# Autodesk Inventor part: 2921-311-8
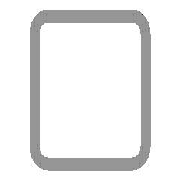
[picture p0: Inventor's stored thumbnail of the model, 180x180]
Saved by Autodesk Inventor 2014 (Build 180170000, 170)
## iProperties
IsCustomPart: 1
Company: NHTSA/VRTC
Created: 2012-02
Part Number: 2921-311-8
Material: Steel, Mild
Description: BENCH FRAME TUBE #8
Document SubType Name: Modeling
Standard: AISC
Designer: Dave Walker
Standards Organization: ANSI
Language: en-US
Size Designation: 1-1/2x1-1/2x1/8 - 24.56
Categories: <MemberInstance><Categories><Category DisplayName="Structural Shapes" InternalName="089c4875-fa83-4c05-b084-43b9cc11f5ed" Mnemonic="GRDR"><CategoryParameter Dis
Stock Number: T.S. 1 1/2 x 1 1/2 x 1/8 x 623.8mm (24.56")
Density: 1 g/cm^3
Project: CHILD SIDE IMPACT SLED
Appearance: Steel
G_L: 24.560 in
Author: Dave Walker
Title: Bench Frame Tube #8
Subject: Child Side Impact Sled
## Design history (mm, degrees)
node "Start plane"
node "End plane"
sketch "Sketch"
  geometry: L1 (-19.05, -12.7)-(-19.05, 12.7); L2 (-12.7, 19.05)-(12.7, 19.05); L3 (19.05, 12.7)-(19.05, -12.7); L4 (12.7, -19.05)-(-12.7, -19.05); L5 (-12.7, 15.875)-(12.7, 15.875); L6 (15.875, 12.7)-(15.875, -12.7); L7 (12.7, -15.875)-(-12.7, -15.875); L8 (-15.875, -12.7)-(-15.875, 12.7); L9 (0, 36.948)-(0, -36.948) reference; L10 (-23.079, 0)-(23.079, 0) reference; A1 r 6.35 centre (-12.7, -12.7) between (-19.05, -12.7) and (-12.7, -19.05); A2 r 6.35 centre (-12.7, 12.7) between (-12.7, 19.05) and (-19.05, 12.7); A3 r 6.35 centre (12.7, 12.7) between (19.05, 12.7) and (12.7, 19.05); A4 r 6.35 centre (12.7, -12.7) between (12.7, -19.05) and (19.05, -12.7); A5 r 3.175 centre (-12.7, 12.7) between (-12.7, 15.875) and (-15.875, 12.7); A6 r 3.175 centre (12.7, 12.7) between (15.875, 12.7) and (12.7, 15.875); A7 r 3.175 centre (12.7, -12.7) between (12.7, -15.875) and (15.875, -12.7); A8 r 3.175 centre (-12.7, -12.7) between (-15.875, -12.7) and (-12.7, -15.875)
  constraints: 16 end point, 16 point on circle, 8 centre point, 8 tangent, 4 parallel, 3 equal radius, 2 perpendicular, 7 other
  dimensions: "d10" = 38.1 distance between parallel lines of L2 L4 (= G_H); "d11" = 38.1 distance between parallel lines of L1 L3 (= G_W); "d12" = 3.175 distance between parallel lines of L3 L6 (= G_T); "d15" = 19.05 distance between parallel lines of L2 L10 (= 0.5 x d10); "d16" = 19.05 distance between parallel lines of L9 L3 (= 0.5 x d11); "d17" = 6.35 radius of A1 (= G_IR)
extrude "Body" new body sketch "Sketch" stored distance "d3" = 623.824 (= G_L); taper "d4" = 0 deg
node "Driven Length"
  sketch "Sketch3"
    geometry: L1 (0, 0)-(10, 0) reference
    constraints: 2 end point, 1 horizontal
  workplane "Work Plane3"
  sketch "Sketch4"
    geometry: L1 (-2, 0)-(12, 0) reference; L2 (-2, 623.824)-(12, 623.824) reference
    dimensions: "d19" = 623.824 distance between parallel lines of L1 L2 (derived)
sketch "Sketch5"
  geometry: L1 (25.4, 0)-(0, 0) reference; L2 (0, 0)-(0, 623.824) reference; L3 (-3.175, 0)-(-3.175, 623.824) reference; L4 (31.75, 0)-(31.75, 623.824) reference; 2 further points
  dimensions: "d21" = 260.35 distance from line of point (12.7, 260.35) L1; "d29" = 19.05 distance from line of L4 point (12.7, 260.35)
hole "Hole1" sketch "Sketch5" at (12.7, 260.35) diameter "d22" = 7.14375; stored, may be unused: countersink angle "d26" = 82 deg, drill point angle "d28" = 118 deg; dims "d23" = 19.05, "d24" = 9.525, "d25" = 6.35, "d27" = 25.4
body "Solid1"
other parameters: "G_W" = 38.1 [user parameter; used in 1 equation term], "G_H" = 38.1 [user parameter; used in 1 equation term], "G_T" = 3.175 [user parameter; used in 1 equation term], "G_IR" = 6.35 [user parameter; used in 1 equation term], "G_L" = 623.824 (= d19) [user parameter; used in 1 equation term], "G_OFFSET_START" = 0 [user parameter; used in 1 equation term], "G_OFFSET_END" = 0 [user parameter; used in 1 equation term], "d13" = 0 (computed from G_OFFSET_START), "d14" = 623.824 (= G_OFFSET_END + B_L), "B_L" = 623.824 [user parameter; used in 1 equation term], "d18" = 90 deg
